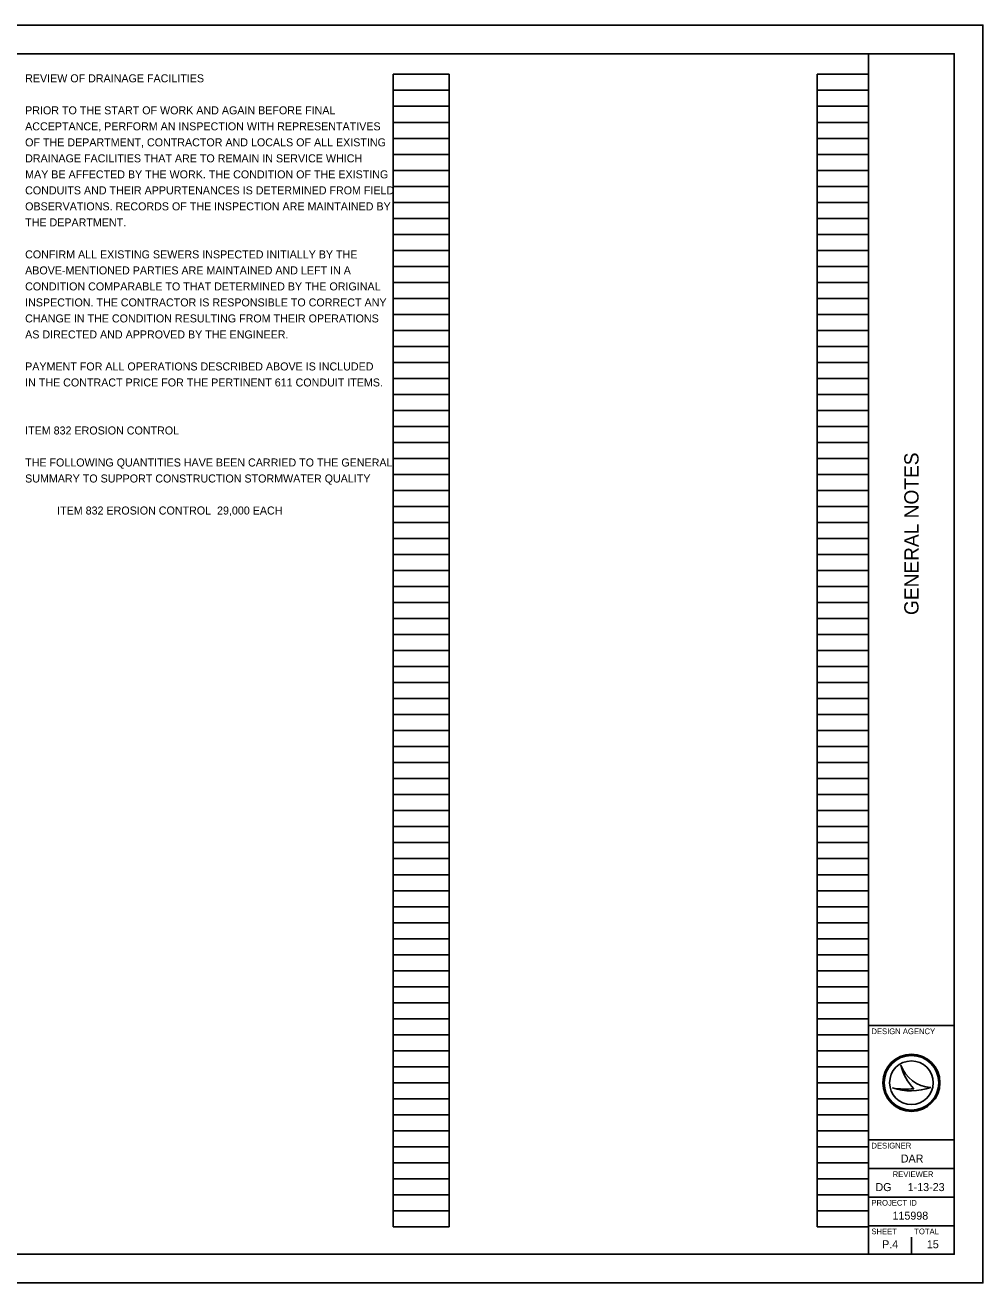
# Model space of a CAD drawing. Extents: x 0 to 34, y 0 to 22.
# Drawn here: x 17.24 to 34, y 0 to 22 of the extents above; entities that cross this region are included whole.
import ezdxf

# ---------------------------------------------------------------- set-up
doc = ezdxf.new("R2010")
doc.units = 0
for name, color, linetype in [('SH_Border', 7, 'Continuous'), ('SH_Cut_Line', 7, 'Continuous'), ('SH_Data', 7, 'Continuous'), ('SH_Text', 7, 'Continuous')]:
    doc.layers.add(name, color=color, linetype=linetype)

msp = doc.modelspace()

# ---------------------------------------------------------------- linework, layer by layer
at = {"layer": 'SH_Border'}
for p, q in [((32, 0.5), (32, 21.5)), ((32, 4.5), (33.5, 4.5)), ((32, 2.5), (33.5, 2.5)), ((32, 2), (33.5, 2)), ((32, 1.5), (33.5, 1.5)), ((32, 1), (33.5, 1))]:
    msp.add_line(p, q, dxfattribs=at)
msp.add_lwpolyline([(1.5, 21.5), (33.5, 21.5), (33.5, 0.5), (1.5, 0.5)], close=True, dxfattribs=at)
at = {"layer": 'SH_Cut_Line'}
msp.add_lwpolyline([(0, 0), (34, 0), (34, 22), (0, 22)], close=True, dxfattribs=at)
at = {"layer": 'SH_Data'}
for p, q in [((23.68, 0.98), (23.68, 21.14)), ((23.68, 21.14), (24.66, 21.14)), ((24.66, 0.98), (24.66, 21.14)), ((31.1, 0.98), (31.1, 21.14)), ((31.1, 21.14), (32, 21.14)), ((32, 0.98), (32, 21.14)), ((23.68, 20.86), (24.66, 20.86)), ((31.1, 20.86), (32, 20.86)), ((23.68, 20.58), (24.66, 20.58)), ((31.1, 20.58), (32, 20.58)), ((23.68, 20.3), (24.66, 20.3)), ((31.1, 20.3), (32, 20.3)), ((23.68, 20.02), (24.66, 20.02)), ((31.1, 20.02), (32, 20.02)), ((23.68, 19.74), (24.66, 19.74)), ((31.1, 19.74), (32, 19.74)), ((23.68, 19.46), (24.66, 19.46)), ((31.1, 19.46), (32, 19.46)), ((23.68, 19.18), (24.66, 19.18)), ((31.1, 19.18), (32, 19.18)), ((23.68, 18.9), (24.66, 18.9)), ((31.1, 18.9), (32, 18.9)), ((23.68, 18.62), (24.66, 18.62)), ((31.1, 18.62), (32, 18.62)), ((23.68, 18.34), (24.66, 18.34)), ((31.1, 18.34), (32, 18.34)), ((23.68, 18.06), (24.66, 18.06)), ((31.1, 18.06), (32, 18.06)), ((23.68, 17.78), (24.66, 17.78)), ((31.1, 17.78), (32, 17.78)), ((23.68, 17.5), (24.66, 17.5)), ((31.1, 17.5), (32, 17.5)), ((23.68, 17.22), (24.66, 17.22)), ((31.1, 17.22), (32, 17.22)), ((23.68, 16.94), (24.66, 16.94)), ((31.1, 16.94), (32, 16.94)), ((23.68, 16.66), (24.66, 16.66)), ((31.1, 16.66), (32, 16.66)), ((23.68, 16.38), (24.66, 16.38)), ((31.1, 16.38), (32, 16.38)), ((23.68, 16.1), (24.66, 16.1)), ((31.1, 16.1), (32, 16.1)), ((23.68, 15.82), (24.66, 15.82)), ((31.1, 15.82), (32, 15.82)), ((23.68, 15.54), (24.66, 15.54)), ((31.1, 15.54), (32, 15.54)), ((23.68, 15.26), (24.66, 15.26)), ((31.1, 15.26), (32, 15.26)), ((23.68, 14.98), (24.66, 14.98)), ((31.1, 14.98), (32, 14.98)), ((23.68, 14.7), (24.66, 14.7)), ((31.1, 14.7), (32, 14.7)), ((23.68, 14.42), (24.66, 14.42)), ((31.1, 14.42), (32, 14.42)), ((23.68, 14.14), (24.66, 14.14)), ((31.1, 14.14), (32, 14.14)), ((23.68, 13.86), (24.66, 13.86)), ((31.1, 13.86), (32, 13.86)), ((23.68, 13.58), (24.66, 13.58)), ((31.1, 13.58), (32, 13.58)), ((23.68, 13.3), (24.66, 13.3)), ((31.1, 13.3), (32, 13.3)), ((23.68, 13.02), (24.66, 13.02)), ((31.1, 13.02), (32, 13.02)), ((23.68, 12.74), (24.66, 12.74)), ((31.1, 12.74), (32, 12.74)), ((23.68, 12.46), (24.66, 12.46)), ((31.1, 12.46), (32, 12.46)), ((23.68, 12.18), (24.66, 12.18)), ((31.1, 12.18), (32, 12.18)), ((23.68, 11.9), (24.66, 11.9)), ((31.1, 11.9), (32, 11.9)), ((23.68, 11.62), (24.66, 11.62)), ((31.1, 11.62), (32, 11.62)), ((23.68, 11.34), (24.66, 11.34)), ((31.1, 11.34), (32, 11.34)), ((23.68, 11.06), (24.66, 11.06)), ((31.1, 11.06), (32, 11.06)), ((23.68, 10.78), (24.66, 10.78)), ((31.1, 10.78), (32, 10.78)), ((23.68, 10.5), (24.66, 10.5)), ((31.1, 10.5), (32, 10.5)), ((23.68, 10.22), (24.66, 10.22)), ((31.1, 10.22), (32, 10.22)), ((23.68, 9.94), (24.66, 9.94)), ((31.1, 9.94), (32, 9.94)), ((23.68, 9.66), (24.66, 9.66)), ((31.1, 9.66), (32, 9.66)), ((23.68, 9.38), (24.66, 9.38)), ((31.1, 9.38), (32, 9.38)), ((23.68, 9.1), (24.66, 9.1)), ((31.1, 9.1), (32, 9.1)), ((23.68, 8.82), (24.66, 8.82)), ((31.1, 8.82), (32, 8.82)), ((23.68, 8.54), (24.66, 8.54)), ((31.1, 8.54), (32, 8.54)), ((23.68, 8.26), (24.66, 8.26)), ((31.1, 8.26), (32, 8.26)), ((23.68, 7.98), (24.66, 7.98)), ((31.1, 7.98), (32, 7.98)), ((23.68, 7.7), (24.66, 7.7)), ((31.1, 7.7), (32, 7.7)), ((23.68, 7.42), (24.66, 7.42)), ((31.1, 7.42), (32, 7.42)), ((23.68, 7.14), (24.66, 7.14)), ((31.1, 7.14), (32, 7.14)), ((23.68, 6.86), (24.66, 6.86)), ((31.1, 6.86), (32, 6.86)), ((23.68, 6.58), (24.66, 6.58)), ((31.1, 6.58), (32, 6.58)), ((23.68, 6.3), (24.66, 6.3)), ((31.1, 6.3), (32, 6.3)), ((23.68, 6.02), (24.66, 6.02)), ((31.1, 6.02), (32, 6.02)), ((23.68, 5.74), (24.66, 5.74)), ((31.1, 5.74), (32, 5.74)), ((23.68, 5.46), (24.66, 5.46)), ((31.1, 5.46), (32, 5.46)), ((23.68, 5.18), (24.66, 5.18)), ((31.1, 5.18), (32, 5.18)), ((23.68, 4.9), (24.66, 4.9)), ((31.1, 4.9), (32, 4.9)), ((23.68, 4.62), (24.66, 4.62)), ((31.1, 4.62), (32, 4.62)), ((23.68, 4.34), (24.66, 4.34)), ((31.1, 4.34), (32, 4.34)), ((23.68, 4.06), (24.66, 4.06)), ((31.1, 4.06), (32, 4.06)), ((23.68, 3.78), (24.66, 3.78)), ((31.1, 3.78), (32, 3.78)), ((32.567, 3.81), (32.567, 3.81)), ((23.68, 3.5), (24.66, 3.5)), ((31.1, 3.5), (32, 3.5)), ((32.417, 3.41), (32.417, 3.41)), ((32.75, 3.5), (32.75, 3.5)), ((33.087, 3.419), (33.087, 3.419)), ((23.68, 3.22), (24.66, 3.22)), ((31.1, 3.22), (32, 3.22)), ((23.68, 2.94), (24.66, 2.94)), ((31.1, 2.94), (32, 2.94)), ((23.68, 2.66), (24.66, 2.66)), ((31.1, 2.66), (32, 2.66)), ((23.68, 2.38), (24.66, 2.38)), ((31.1, 2.38), (32, 2.38)), ((23.68, 2.1), (24.66, 2.1)), ((31.1, 2.1), (32, 2.1)), ((23.68, 1.82), (24.66, 1.82)), ((31.1, 1.82), (32, 1.82)), ((23.68, 1.54), (24.66, 1.54)), ((31.1, 1.54), (32, 1.54)), ((23.68, 1.26), (24.66, 1.26)), ((31.1, 1.26), (32, 1.26)), ((23.68, 0.98), (24.66, 0.98)), ((31.1, 0.98), (32, 0.98)), ((32.375, 0.675), (32.375, 0.675)), ((32.75, 0.5), (32.75, 0.8))]:
    msp.add_line(p, q, dxfattribs=at)
for radius in [0.5, 0.477, 0.477, 0.382]:
    msp.add_circle((32.75, 3.5), radius, dxfattribs=at)
for centre, radius, start, end in [((33.116, 3.998), 0.58, 198.9257, 198.9319), ((33.347, 3.97), 0.796, 191.6379, 191.6421), ((33.116, 3.998), 0.58, 198.9319, 267.1657), ((33.347, 3.97), 0.796, 191.6421, 226.0947), ((32.739, 4.37), 1.013, 251.4576, 290.0832), ((32.648, 4.654), 1.266, 259.4964, 259.4995), ((32.739, 4.37), 1.013, 251.4527, 251.4576), ((32.648, 4.654), 1.266, 259.4995, 276.6672)]:
    msp.add_arc(centre, radius, start, end, dxfattribs=at)

# ---------------------------------------------------------------- texts
msp.add_text('GENERAL NOTES', height=0.25, rotation=90, dxfattribs=at).set_placement((32.875, 11.682))
for s, height, p in [('DESIGN AGENCY', 0.1, (32.05, 4.35)), ('DESIGNER', 0.1, (32.05, 2.35)), ('DAR', 0.14, (32.564, 2.105)), ('REVIEWER', 0.1, (32.422, 1.85)), ('DG', 0.14, (32.121, 1.605)), ('1-13-23', 0.14, (32.685, 1.605)), ('PROJECT ID', 0.1, (32.05, 1.35)), ('115998', 0.14, (32.419, 1.105)), ('SHEET', 0.1, (32.05, 0.85)), ('TOTAL', 0.1, (32.8, 0.85)), ('P.4', 0.14, (32.237, 0.605)), ('15', 0.14, (33.02, 0.605))]:
    msp.add_text(s, height=height, dxfattribs=at).set_placement(p)
at = {"layer": 'SH_Text'}
for s, p in [('REVIEW OF DRAINAGE FACILITIES', (17.24, 21)), ('PRIOR TO THE START OF WORK AND AGAIN BEFORE FINAL', (17.24, 20.44)), ('ACCEPTANCE, PERFORM AN INSPECTION WITH REPRESENTATIVES', (17.24, 20.16)), ('OF THE DEPARTMENT, CONTRACTOR AND LOCALS OF ALL EXISTING', (17.24, 19.88)), ('DRAINAGE FACILITIES THAT ARE TO REMAIN IN SERVICE WHICH', (17.24, 19.6)), ('MAY BE AFFECTED BY THE WORK. THE CONDITION OF THE EXISTING', (17.24, 19.32)), ('CONDUITS AND THEIR APPURTENANCES IS DETERMINED FROM FIELD', (17.24, 19.04)), ('OBSERVATIONS. RECORDS OF THE INSPECTION ARE MAINTAINED BY', (17.24, 18.76)), ('THE DEPARTMENT.', (17.24, 18.48)), ('CONFIRM ALL EXISTING SEWERS INSPECTED INITIALLY BY THE', (17.24, 17.92)), ('ABOVE-MENTIONED PARTIES ARE MAINTAINED AND LEFT IN A', (17.24, 17.64)), ('CONDITION COMPARABLE TO THAT DETERMINED BY THE ORIGINAL', (17.24, 17.36)), ('INSPECTION. THE CONTRACTOR IS RESPONSIBLE TO CORRECT ANY', (17.24, 17.08)), ('CHANGE IN THE CONDITION RESULTING FROM THEIR OPERATIONS', (17.24, 16.8)), ('AS DIRECTED AND APPROVED BY THE ENGINEER.', (17.24, 16.52)), ('PAYMENT FOR ALL OPERATIONS DESCRIBED ABOVE IS INCLUDED', (17.24, 15.96)), ('IN THE CONTRACT PRICE FOR THE PERTINENT 611 CONDUIT ITEMS.', (17.24, 15.68)), ('ITEM 832 EROSION CONTROL', (17.24, 14.84)), ('THE FOLLOWING QUANTITIES HAVE BEEN CARRIED TO THE GENERAL', (17.24, 14.28)), ('SUMMARY TO SUPPORT CONSTRUCTION STORMWATER QUALITY', (17.24, 14)), ('ITEM 832 EROSION CONTROL  29,000 EACH', (17.8, 13.44))]:
    msp.add_text(s, height=0.14, dxfattribs=at).set_placement(p)

doc.saveas('drawing.dxf')
